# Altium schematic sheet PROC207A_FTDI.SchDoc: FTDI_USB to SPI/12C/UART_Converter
size 431 x 279 mm; Date: Not shown in title block; ApprovedBy: Not shown in title block; CheckedBy: Not shown in title block; Author: Not shown in title block; CompanyName: Not shown in title block; DrawnBy: Mistral; Engineer: Not shown in title block; Organization: Not shown in title block; Address1: Not shown in title block; Address2: Not shown in title block; Address3: Not shown in title block; Address4: Not shown in title block; DocumentNumber: 14; Revision: Use project parameter SCH_Rev; SheetNumber: 15; SheetTotal: 18; PageSetup: Record=PageOptions¦CenterHorizontal=True¦CenterVertical=True¦PrintScale=1.00¦XCorrection=1.00¦YCorrection=1.00¦PrintKind=0¦BorderSize=5000000¦LeftOffset=0¦BottomOffset=0¦Orientation=2¦PaperLength=1000¦PaperWidth=1000¦Scale=100¦PaperSource=15¦PrintQuality=600¦MediaType=1¦DitherType=10¦PaperKind=Letter¦PrintScaleMode=1
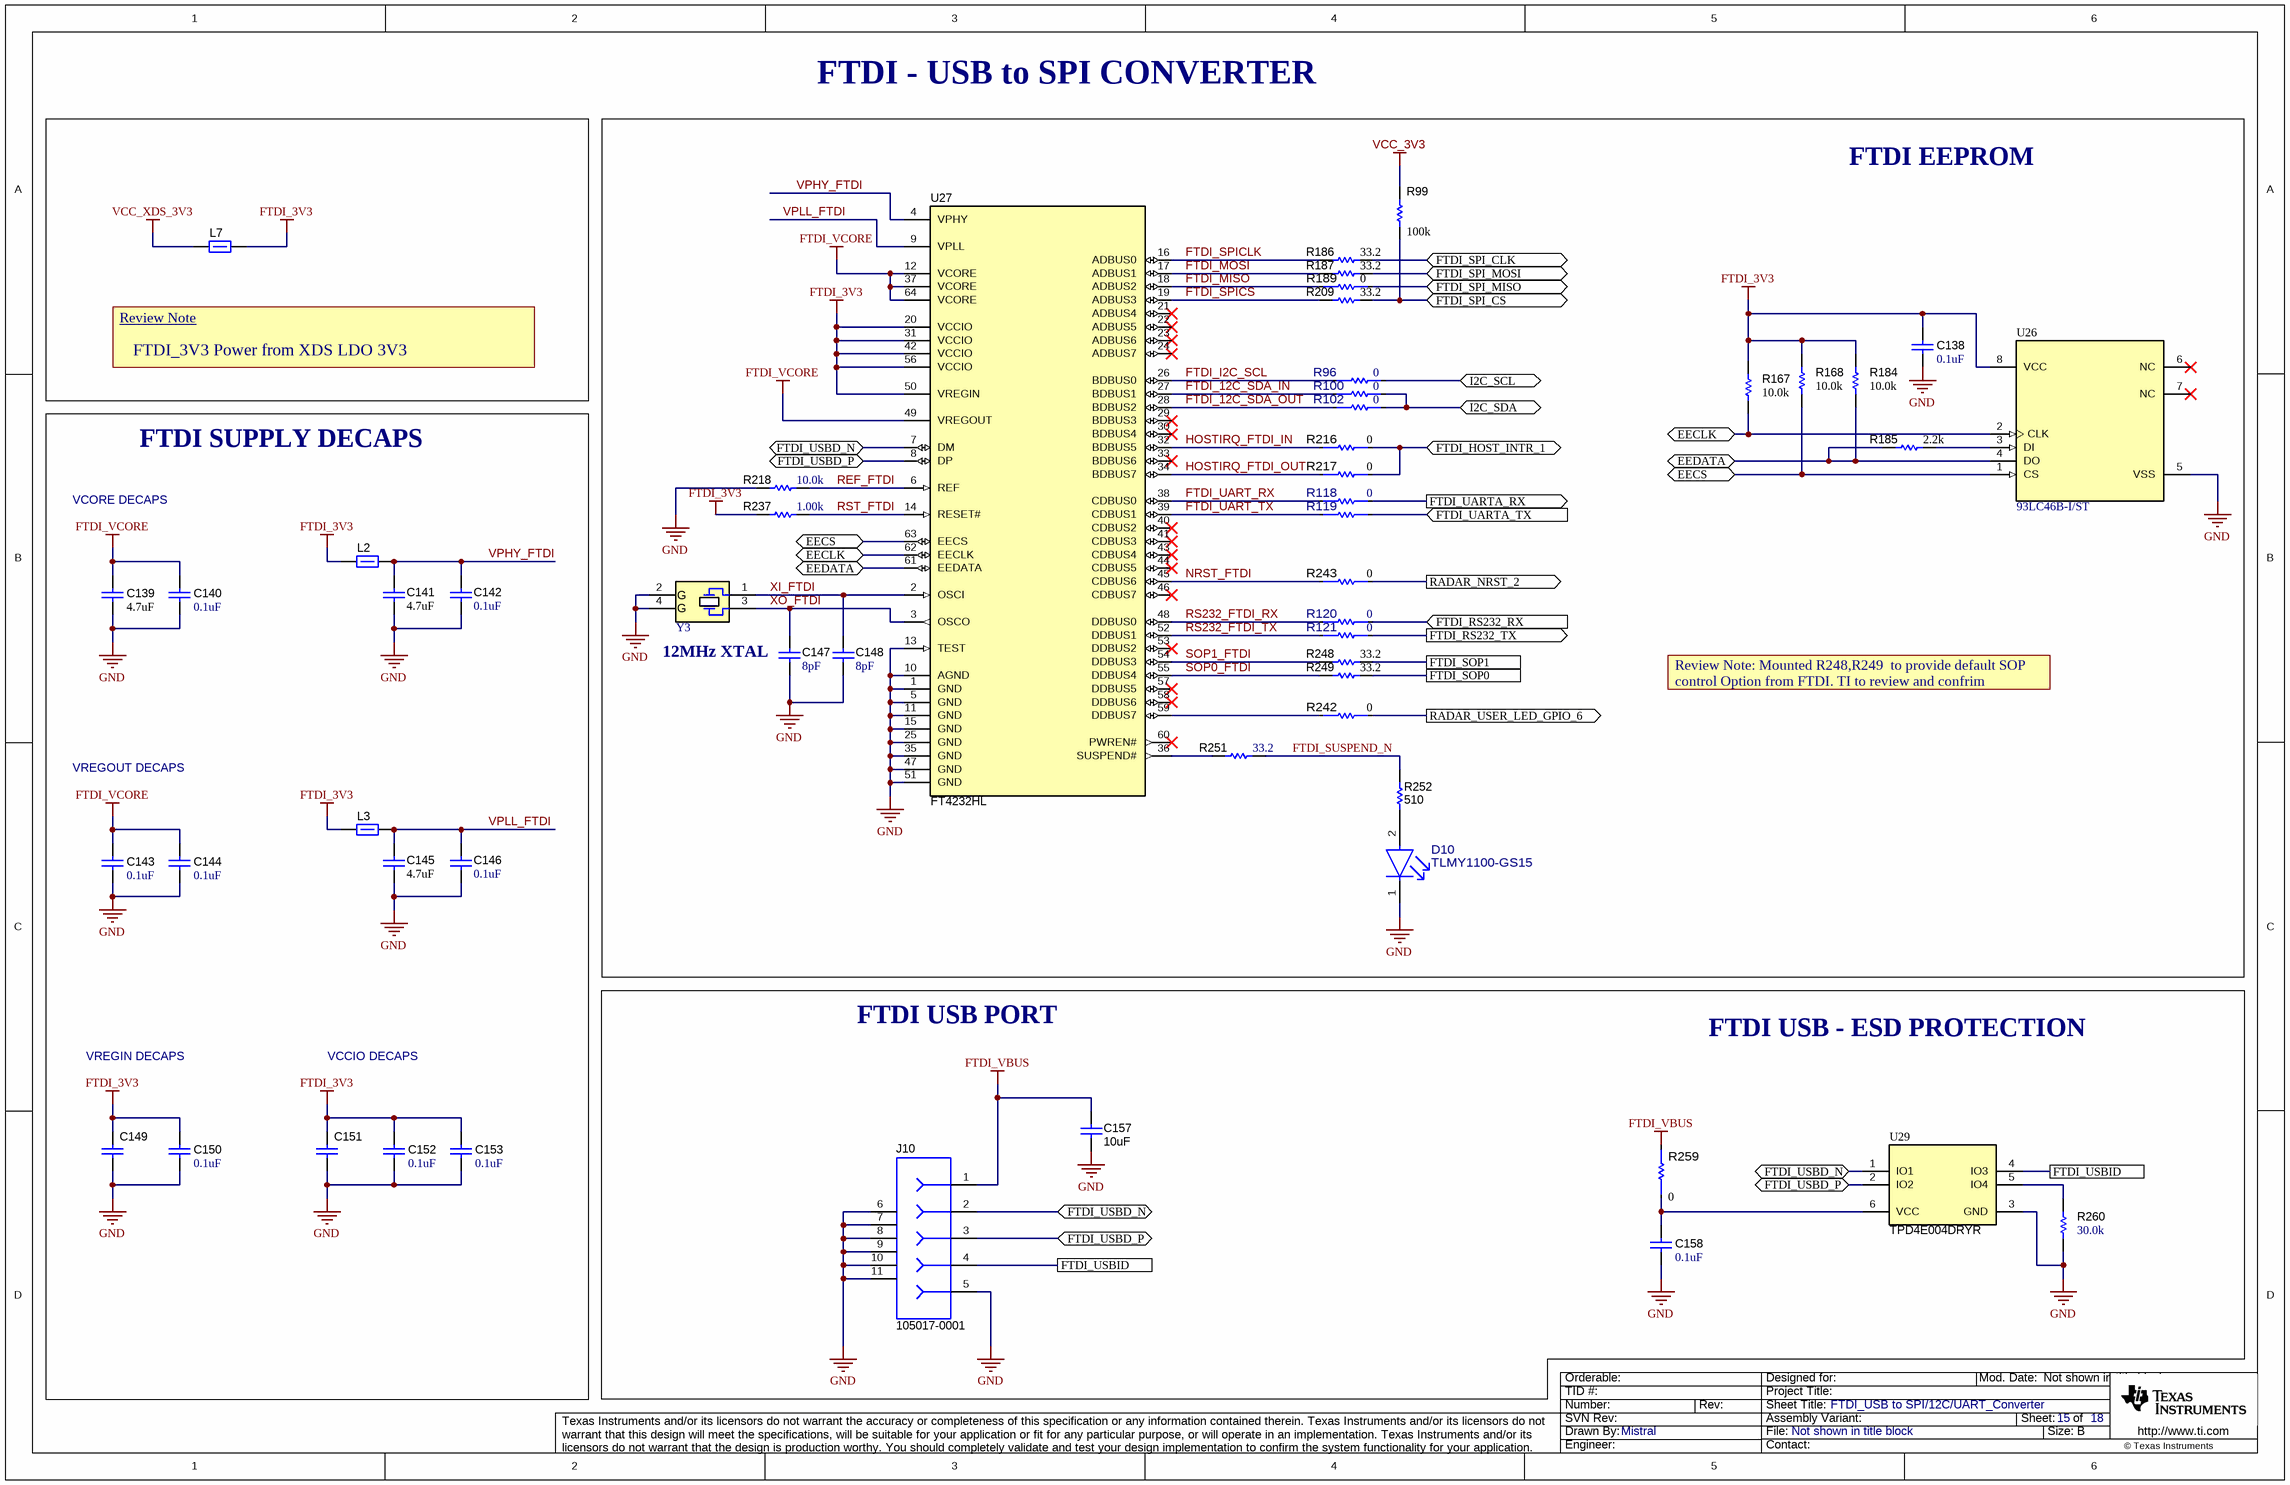
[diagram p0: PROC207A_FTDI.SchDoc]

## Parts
C138  ValueDisplayed: 0.1uF  [0402]  (hidden comment: GCM155R71H104KE02D)
C139  ValueDisplayed: 4.7uF  [0603L]  (hidden comment: C1608X7S1A475K080AC)
C140  ValueDisplayed: 0.1uF  [0402]  (hidden comment: GCM155R71H104KE02D)
C141  ValueDisplayed: 4.7uF  [0603L]  (hidden comment: C1608X7S1A475K080AC)
C142  ValueDisplayed: 0.1uF  [0402]  (hidden comment: GCM155R71H104KE02D)
C143  ValueDisplayed: 0.1uF  [0402]  (hidden comment: GCM155R71H104KE02D)
C144  ValueDisplayed: 0.1uF  [0402]  (hidden comment: GCM155R71H104KE02D)
C145  ValueDisplayed: 4.7uF  [0603L]  (hidden comment: C1608X7S1A475K080AC)
C146  ValueDisplayed: 0.1uF  [0402]  (hidden comment: GCM155R71H104KE02D)
C147  Cap_F: 8pF  [0402L]  (hidden comment: GCM1555C1H8R0DA16D)
C148  Cap_F: 8pF  [0402L]  (hidden comment: GCM1555C1H8R0DA16D)
C149  CL10B105KA8NNNC  [0603]  (value not drawn)
C150  ValueDisplayed: 0.1uF  [0402]  (hidden comment: GCM155R71H104KE02D)
C151  CL10B105KA8NNNC  [0603]  (value not drawn)
C152  ValueDisplayed: 0.1uF  [0402]  (hidden comment: GCM155R71H104KE02D)
C153  ValueDisplayed: 0.1uF  [0402]  (hidden comment: GCM155R71H104KE02D)
C157  ValueDisplayed: 10uF  [0603S]  (hidden comment: GRT188R61A106KE13D)
C158  ValueDisplayed: 0.1uF  [0402]  (hidden comment: GCM155R71H104KE02D)
D10  TLMY1100-GS15  [FP-TLMY1100-GS15_0603-MFG]
J10  105017-0001  [CONN_105017-0001]
L2  BLM15HG601SN1D  [0402L]  (value not drawn)
L3  BLM15HG601SN1D  [0402L]  (value not drawn)
L7  BLM15HG601SN1D  [0402L]  (value not drawn)
R96  value 0  [FP-ERJ-2GE0R00X_0402-MFG]  (hidden comment: ERJ-2GE0R00X)
R99  ValueDisplayed: 100k  [0402]  (hidden comment: CRCW0402100KFKED)
R100  value 0  [FP-ERJ-2GE0R00X_0402-MFG]  (hidden comment: ERJ-2GE0R00X)
R102  value 0  [FP-ERJ-2GE0R00X_0402-MFG]  (hidden comment: ERJ-2GE0R00X)
R118  value 0  [FP-ERJ-2GE0R00X_0402-MFG]  (hidden comment: ERJ-2GE0R00X)
R119  ERJ-2GE0R00X  [FP-ERJ-2GE0R00X_0402-MFG]  (value not drawn)
R120  value 0  [FP-ERJ-2GE0R00X_0402-MFG]  (hidden comment: ERJ-2GE0R00X)
R121  value 0  [FP-ERJ-2GE0R00X_0402-MFG]  (hidden comment: ERJ-2GE0R00X)
R167  ValueDisplayed: 10.0k  [0402L]  (hidden comment: CRCW040210K0FKED)
R168  ValueDisplayed: 10.0k  [0402L]  (hidden comment: CRCW040210K0FKED)
R184  ValueDisplayed: 10.0k  [0402L]  (hidden comment: CRCW040210K0FKED)
R185  ValueDisplayed: 2.2k  [0402L]  (hidden comment: CRCW04022K20JNED)
R186  ValueDisplayed: 33.2  [0402]  (hidden comment: CRCW040233R2FKED)
R187  ValueDisplayed: 33.2  [0402]  (hidden comment: CRCW040233R2FKED)
R189  value 0  [FP-ERJ-2GE0R00X_0402-MFG]  (hidden comment: ERJ-2GE0R00X)
R209  ValueDisplayed: 33.2  [0402]  (hidden comment: CRCW040233R2FKED)
R216  value 0  [FP-ERJ-2GE0R00X_0402-MFG]  (hidden comment: ERJ-2GE0R00X)
R217  value 0  [FP-ERJ-2GE0R00X_0402-MFG]  (hidden comment: ERJ-2GE0R00X)
R218  ValueDisplayed: 10.0k  [0402L]  (hidden comment: CRCW040210K0FKED)
R237  ValueDisplayed: 1.00k  [0402]  (hidden comment: ERJ-2RKF1001X)
R242  value 0  [FP-ERJ-2GE0R00X_0402-MFG]  (hidden comment: ERJ-2GE0R00X)
R243  value 0  [FP-ERJ-2GE0R00X_0402-MFG]  (hidden comment: ERJ-2GE0R00X)
R248  ValueDisplayed: 33.2  [0402]  (hidden comment: CRCW040233R2FKED)
R249  ValueDisplayed: 33.2  [0402]  (hidden comment: CRCW040233R2FKED)
R251  ValueDisplayed: 33.2  [0402]  (hidden comment: CRCW040233R2FKED)
R252  ValueDisplayed: 510  [0402L]  (hidden comment: ERJ-2GEJ511X)
R259  value 0  [FP-ERJ-2GE0R00X_0402-MFG]  (hidden comment: ERJ-2GE0R00X)
R260  ValueDisplayed: 30.0k  [0402L]  (hidden comment: CRCW040230K0FKED)
U26  93LC46B-I/ST  [TSSOP-8]
U27  FT4232HL  [LQFP64_N]
U29  TPD4E004DRYR  [DRY0006A]
Y3  NX3225SA-12.000M-STD-CRS-2  [NDK_NX3225SA]  (value not drawn)

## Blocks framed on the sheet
FTDI_3V3 Power from XDS LDO 3V3: L7
FTDI EEPROM: C138 C147 C148 D10 R96 R99 R100 R102 R118-R121 R167 R168 R184-R187 R189 R209 R216-R218 R237 R242 R243 R248 R249 R251 R252 U26 U27 Y3
FTDI SUPPLY DECAPS: C139-C146 C149-C153 L2 L3

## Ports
EECLK (bidir), EECS (bidir), EEDATA (bidir), FTDI_HOST_INTR_1 (bidir), FTDI_RS232_RX (in), FTDI_RS232_TX (out), FTDI_SOP0, FTDI_SOP1, FTDI_SPI_CLK (bidir), FTDI_SPI_CS (bidir), FTDI_SPI_MISO (bidir), FTDI_SPI_MOSI (bidir), FTDI_UARTA_RX (out), FTDI_UARTA_TX (in), FTDI_USBD_N (bidir), FTDI_USBD_P (bidir), FTDI_USBID, I2C_SCL (bidir), I2C_SDA (bidir), RADAR_NRST_2 (out), RADAR_USER_LED_GPIO_6 (out)

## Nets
FTDI_3V3: C138.1 C149.2 C150.1 C151.2 C152.1 C153.1 L2.1 L3.1 L7.2 R167.2 R168.2 R184.2 R237.1 U26.8(VCC) U27.20(VCCIO) U27.31(VCCIO) U27.42(VCCIO) U27.50(VREGIN) U27.56(VCCIO)
FTDI_VBUS: C157.2 J10.1 R259.2
FTDI_VCORE: C139.1 C140.1 C143.1 C144.1 U27.12(VCORE) U27.37(VCORE) U27.49(VREGOUT) U27.64(VCORE)
GND: C138.2 C139.2 C140.2 C141.2 C142.1 C143.2 C144.2 C145.2 C146.1 C147.2 C148.2 C149.1 C150.2 C151.1 C152.2 C153.2 C157.1 C158.2 D10.1(C) J10.5 J10.6 J10.7 J10.8 J10.9 J10.10 J10.11 R218.1 R260.1 U26.5(VSS) U27.1(GND) U27.5(GND) U27.10(AGND) U27.11(GND) U27.13(TEST) U27.15(GND) U27.25(GND) U27.35(GND) U27.47(GND) U27.51(GND) U29.3(GND) Y3.2(GND) Y3.4(GND)
VCC_3V3: R99.2
VCC_XDS_3V3: L7.1
EECLK: R167.1 U26.2(CLK) U27.62(EECLK) ; port EECLK
EECS: R168.1 U26.1(CS) U27.63(EECS) ; port EECS
EEDATA: R184.1 R185.1 U26.4(DO) U27.61(EEDATA) ; port EEDATA
FTDI_12C_SDA_IN: R100.1 U27.27(BDBUS1)
FTDI_12C_SDA_OUT: R102.1 U27.28(BDBUS2)
FTDI_HOST_INTR_1: R216.2 R217.2 ; port FTDI_HOST_INTR_1
FTDI_I2C_SCL: R96.1 U27.26(BDBUS0)
FTDI_MISO: R189.1 U27.18(ADBUS2)
FTDI_MOSI: R187.1 U27.17(ADBUS1)
FTDI_RS232_RX: R120.2 ; port FTDI_RS232_RX
FTDI_RS232_TX: R121.2 ; port FTDI_RS232_TX
FTDI_SOP0: R249.2 ; port FTDI_SOP0
FTDI_SOP1: R248.2 ; port FTDI_SOP1
FTDI_SPI_CLK: R186.2 ; port FTDI_SPI_CLK
FTDI_SPI_CS: R99.1 R209.2 ; port FTDI_SPI_CS
FTDI_SPI_MISO: R189.2 ; port FTDI_SPI_MISO
FTDI_SPI_MOSI: R187.2 ; port FTDI_SPI_MOSI
FTDI_SPICLK: R186.1 U27.16(ADBUS0)
FTDI_SPICS: R209.1 U27.19(ADBUS3)
FTDI_SUSPEND_N: R251.2 R252.1
FTDI_UART_RX: R118.1 U27.38(CDBUS0)
FTDI_UART_TX: R119.1 U27.39(CDBUS1)
FTDI_UARTA_RX: R118.2 ; port FTDI_UARTA_RX
FTDI_UARTA_TX: R119.2 ; port FTDI_UARTA_TX
FTDI_USBD_N: J10.2 U27.7(DM) U29.1(IO1) ; port FTDI_USBD_N
FTDI_USBD_P: J10.3 U27.8(DP) U29.2(IO2) ; port FTDI_USBD_P
FTDI_USBID: J10.4 U29.4(IO3) ; port FTDI_USBID
HOSTIRQ_FTDI_IN: R216.1 U27.32(BDBUS5)
HOSTIRQ_FTDI_OUT: R217.1 U27.34(BDBUS7)
I2C_SCL: R96.2 ; port I2C_SCL
I2C_SDA: R100.2 R102.2 ; port I2C_SDA
NRST_FTDI: R243.1 U27.45(CDBUS6)
RADAR_NRST_2: R243.2 ; port RADAR_NRST_2
RADAR_USER_LED_GPIO_6: R242.2 ; port RADAR_USER_LED_GPIO_6
REF_FTDI: R218.2 U27.6(REF)
RS232_FTDI_RX: R120.1 U27.48(DDBUS0)
RS232_FTDI_TX: R121.1 U27.52(DDBUS1)
RST_FTDI: R237.2 U27.14(RESET#)
SOP0_FTDI: R249.1 U27.55(DDBUS4)
SOP1_FTDI: R248.1 U27.54(DDBUS3)
VPHY_FTDI: C141.1 C142.2 L2.2 U27.4(VPHY)
VPLL_FTDI: C145.1 C146.2 L3.2 U27.9(VPLL)
XI_FTDI: C148.1 U27.2(OSCI) Y3.1
XO_FTDI: C147.1 U27.3(OSCO) Y3.3
NetC158_1: C158.1 R259.1 U29.6(VCC)
NetD10_2: D10.2(A) R252.2
NetR185_2: R185.2 U26.3(DI)
NetR242_1: R242.1 U27.59(DDBUS7)
NetR251_1: R251.1 U27.36(SUSPEND#)
NetR260_2: R260.2 U29.5(IO4)

Not connected (* = marked no-connect by the designer): U26 6(NC)* 7(NC)*; U27 21(ADBUS4)* 22(ADBUS5)* 23(ADBUS6)* 24(ADBUS7)* 29(BDBUS3)* 30(BDBUS4)* 33(BDBUS6)* 40(CDBUS2)* 41(CDBUS3)* 43(CDBUS4)* 44(CDBUS5)* 46(CDBUS7)* 53(DDBUS2)* 57(DDBUS5)* 58(DDBUS6)* 60(PWREN#)*

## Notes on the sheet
- FTDI - USB to SPI CONVERTER
- Review Note
- VCORE DECAPS
- 12MHz XTAL
- Review Note: Mounted R248,R249  to provide default SOP control Option from FTDI. TI to review and confrim
- VREGOUT DECAPS
- FTDI USB PORT
- VREGIN DECAPS
- VCCIO DECAPS
- FTDI USB - ESD PROTECTION

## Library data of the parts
C138 C140 C142-C144 C146 C150 C152 C153 C158 = CMP-0006356-2: CAP, CERM, 0.1 uF, 50 V, +/- 10%, X7R, AEC-Q200 Grade 1, 0402; Manufacturer: MuRata; TaMin_C: -55°C; Polarized: N; SizeAreaWB_mm2: 3; U/M: EA; Value: 0.1uF; TaMax_C: 125°C; SizeZ_mm: 0.6; SizeX_mm: 1; SizeY_mm: 0.5; Value2: 50V; AEC Qualified: Y; Cap_F: 100nF; AEC Category: Q200; Value1: Unknown
C139 C141 C145 = CMP-0007058-4: CAP, CERM, 4.7 uF, 10 V, +/- 10%, X7S, 0603; Manufacturer: TDK; TaMin_C: -55°C; Polarized: N; SizeAreaWB_mm2: 4.68; Value1: Unknown; U/M: EA; Value: 4.7uF; TaMax_C: 125°C; SizeZ_mm: 1; SizeX_mm: 1.6; SizeY_mm: 0.8; Cap_Case: 0603; Value2: 10V; SizeArea_mm2: 1.28; CompType: Capacitor; Cap_F: 4.7µF; AEC Category: Q200
C147 C148 = CMP-0087060-3: Cap Ceramic 8pF 50V C0G 0.5pF SMD 0402 125C Paper T/R; Manufacturer: Murata Electronics North America; AEC Qualified: Yes; TempCo: 30ppm/°C; AEC Grade: Grade 1; SizeZ_mm: 0.55mm
C149 C151 = CMP-0086540-3: CAP, 1uF, 25V, ±10%, X7R, 0603; Manufacturer: Samsung; TempCo: 15%; SizeZ_mm: 0.9mm; AEC Qualified: No; Cap_F: 1µF; Symbol Name: SYM-CL10B105KA8NNNC
C157 = CMP-0007497-5: CAP, CERM, 10 uF, 10 V, +/- 10%, X5R, 0603; Manufacturer: MuRata; Polarized: N; Value: 10uF; U/M: EA; Cap_F: 10µF; Tolerance_%: 20%; Value1: Unknown; VDC_V: 10V; TempCo: X7R; TaMin_C: -55°C; TaMax_C: 125°C; Cap_Case: 0603; SizeArea_mm2: 1.28; SizeAreaWB_mm2: 4.68; SizeX_mm: 1.6; SizeY_mm: 0.8; SizeZ_mm: 1; AEC Category: Q200
D10 = CMP-0121062-1: Yellow 589nm LED Indication - Discrete 2.1V 0603 (1608 Metric); Manufacturer: Vishay; Angle: 160°; LambdaP: 591nm; Power_TotalModule: 90mW; SizeZ_mm: 0.65mm; Tjmax_C: 120°C; Vr_V: 12V; AEC Grade: Grade 3; AEC Qualified: Yes; Forward Current: 20mA; Led Orientation: Top View; Luminous Intensity: 80mcd; TaMax_C: +100°C; TaMin_C: -40°C
J10 = CMP-0055293-1: Connector, Receptacle, Micro-USB Type B, R/A, Bottom Mount SMT; Manufacturer: Molex; CNHeader: FALSE; Green_Lifecycle: Active; Gender: Female; Green_REACh: Passed; CompType: USB; CT: TRUE
L2 L3 L7 = CMP-0081523-1: Ferrite Bead, 600 ohm @ 100 MHz, 0.3 A, 0402; Manufacturer: MuRata; SizeAreaWB_mm2: 3; SizeArea_mm2: 0.5; Value: 600 ohm; SizeZ_mm: 0.6; Imax_A: 3dA; ZTyp@100MHz_Ohm: 600; Value2: 0.3A; Value1: 0.7 ohm; DCR_ohm: 7d; SizeX_mm: 1; Ztyp@1GHz_Ohm: 1k
R96 R100 R102 R118 R120 R121 R189 R216 R217 R242 R243 R259 = CMP-0002710-1: 0 Ohms Jumper Chip Resistor 0402 (1005 Metric) Automotive AEC-Q200 Thick Film; Manufacturer: Panasonic; SizeZ_mm: 0.4mm; AEC Qualified: Yes; AEC Grade: Grade 0; Power: 100mW
R99 = CMP-0025950-3: RES, 100 k, 1%, 0.063 W, AEC-Q200 Grade 0, 0402; Manufacturer: Vishay-Dale; Power_W: 63mW; TempCo: 100 ppm/C; Value: 100k; EIA_Code: E96; SizeX_mm: 1; SizeY_mm: 0.5; SizeZ_mm: 0.6; Value2: 0.063W; AEC Qualified: Y; VDC_V: 50V; AEC Category: Q200; AEC Grade: 0
R119 = CMP-0002710-1: 0 Ohms Jumper Chip Resistor 0402 (1005 Metric) Automotive AEC-Q200 Thick Film; Manufacturer: Panasonic; Value: 0; SizeZ_mm: 0.4mm; AEC Qualified: Yes; AEC Grade: Grade 0; Power: 100mW
R167 R168 R184 R218 = CMP-0025958-3: RES, 10.0 k, 1%, 0.063 W, AEC-Q200 Grade 0, 0402; Manufacturer: Vishay-Dale; Power_W: 63mW; TempCo: 100 ppm/C; Value_Code: 10k0; Value: 10.0k; EIA_Code: E96; Res_ohm: 10k; SizeX_mm: 1; SizeY_mm: 0.5; SizeZ_mm: 0.6; Value2: 0.063W; AEC Qualified: Y; VDC_V: 50V; AEC Category: Q200; AEC Grade: 0
R185 = CMP-0026890-5: RES, 2.2 k, 5%, 0.063 W, AEC-Q200 Grade 0, 0402; Manufacturer: Vishay-Dale; Power_W: 63mW; TempCo: 200 ppm/C; Value_Code: 2k20; Value: 2.2k; EIA_Code: E24; SizeX_mm: 1; SizeY_mm: 0.5; SizeZ_mm: 0.6; Value2: 0.063W; AEC Qualified: Y; VDC_V: 50V; AEC Category: Q200; AEC Grade: 0
R186 R187 R209 R248 R249 R251 = CMP-0026299-2: RES, 33.2, 1%, 0.063 W, AEC-Q200 Grade 0, 0402; Manufacturer: Vishay-Dale; Power_W: 63mW; TempCo: 100 ppm/C; Value_Code: 33R2; Value: 33.2; EIA_Code: E96; SizeX_mm: 1; SizeY_mm: 0.5; SizeZ_mm: 0.6; Value2: 0.063W; AEC Qualified: Y; VDC_V: 50V; AEC Category: Q200; AEC Grade: 0
R237 = CMP-0026657-1: RES, 1.00 k, 1%, 0.1 W, 0402; Manufacturer: Panasonic; Power_W: 100mW; TempCo: 100 ppm/C; Value_Code: 1k00; Value: 1.00k; EIA_Code: E96; Res_ohm: 1k; SizeX_mm: 1; SizeY_mm: 0.5; SizeZ_mm: 0.6; Value2: 0.1W; VDC_V: 50V; AEC Category: Q200; U/M: EA
R252 = CMP-0078212-1: RES, 510, 5%, 0.1 W, AEC-Q200 Grade 0, 0402; Manufacturer: Panasonic; Value_Code: 510R; SizeArea_mm2: 0.5; AEC Qualified: Y; AEC Category: Q200; Value: 510; SizeZ_mm: 0.6; EIA_Code: E24; TempCo: 200 ppm/C; AEC Grade: 0; Power_W: 100mW; VDC_V: 50V; Value2: 0.1W; U/M: EA; SizeX_mm: 1
R260 = CMP-0078244-2: RES, 30.0 k, 1%, 0.063 W, AEC-Q200 Grade 0, 0402; Manufacturer: Vishay-Dale; Power_W: 63mW; Green_Lifecycle: Active; TempCo: 100 ppm/C; Value_Code: 30k0; Green_REACh: Passed; Value: 30.0k; Res_ohm: 30k; SizeX_mm: 1; SizeY_mm: 0.5; SizeZ_mm: 0.6; Value2: 0.063W; AEC Qualified: Y; VDC_V: 50V; AEC Grade: 0; AEC Category: Q200
U26 = CMP-0081524-1: 1K Microwire Compatible Serial EEPROM, TSSOP-8; Manufacturer: Microchip; SizeArea_mm2: 19.2; SizeAreaWB_mm2: 42; SizeY_mm: 3; SizeZ_mm: 1.2; SizeX_mm: 6.4
U27 = CMP-0004747-1: Quad High Speed USB to Multipurpose UART/MPSSE IC; Manufacturer: FTDI
U29 = CMP-0043115-3: 4-Channel ESD Protection Array for High-Speed Data Interfaces, DRY0006A (USON-6); Manufacturer: Texas Instruments; IO Leakage Current(nA): 1; USB High Speed: TRUE; IO Capacitance(Typ)(pF): 1.6; Eco-Plan: Green (RoHS & no Sb/Br); IEC 61000-4-2 Contact(+/- kV): 8; Breakdown Voltage(Min)(V): 6; IEC 61000-4-2 Air-Gap(+/- kV): 12; AEC Category: Q200; AEC Qualified: N; CompType: IC; SizeAreaWB_mm2: 4.9; SizeArea_mm2: 1.45; SizeX_mm: 1.0; SizeZ_mm: 0.6; Rating: Catalog
Y3 = CMP-0081529-1: Crystal, 12 MHz, 15 ppm, 8 pF, AEC-Q200 Grade 1, SMD; Manufacturer: NDK; TaMin_C: -40°C; Frequency Tolerance: 15 ppm; Frequency Stability: 50 ppm; Load Capacitance: 8 pF; Frequency_Fixed: 12MHz; TaMax_C: 125°C; AEC Qualified: Y; AEC Grade: 1; AEC Category: Q200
